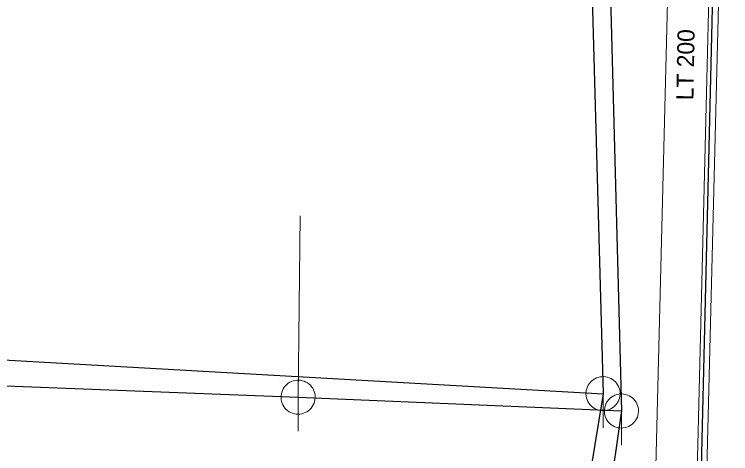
# Model space of a CAD drawing. Extents: x -725153 to -724843, y -978146 to -977794.
# Drawn here: x -724972.4 to -724930.43, y -977958.59 to -977932.83 of the extents above; entities that cross this region are included whole.
import ezdxf

# ---------------------------------------------------------------- set-up
doc = ezdxf.new("R2010")
doc.units = 0
doc.header["$LTSCALE"] = 0.32
doc.layers.add('1', color=7, linetype='Continuous')
for name, color, linetype, lineweight in [('11', 7, 'Continuous', 13), ('13', 7, 'Continuous', 13), ('14', 7, 'Continuous', 25), ('17', 7, 'Continuous', 25), ('2', 7, 'Continuous', 13), ('22', 7, 'Continuous', 13)]:
    doc.layers.add(name, color=color, linetype=linetype, lineweight=lineweight)

msp = doc.modelspace()

# ---------------------------------------------------------------- linework, layer by layer
at = {"layer": '11'}
msp.add_line((-724955.647, -977944.651), (-724955.774, -977955.278), dxfattribs=at)
at = {"layer": '13'}
msp.add_lwpolyline([(-724940.017, -977883.887), (-724940.44, -977904), (-724931.032, -977904.072), (-724932.482, -977963.618)], dxfattribs=at)
at = {"layer": '14'}
for p, q in [((-724938.885, -977919.216), (-724937.906, -977955.074)), ((-724937.758, -977920.649), (-724936.828, -977956.089)), ((-724985.605, -977952.39), (-724937.906, -977955.074)), ((-724987.208, -977954.063), (-724955.774, -977955.278)), ((-724937.906, -977955.074), (-724939.603, -977965.365)), ((-724955.774, -977955.278), (-724936.828, -977956.089)), ((-724936.828, -977956.089), (-724938.046, -977964.432))]:
    msp.add_line(p, q, dxfattribs=at)
at = {"layer": '17'}
msp.add_lwpolyline([(-724932.296, -977965.921), (-724930.809, -977903.881), (-724940.261, -977903.85), (-724939.557, -977875.228), (-724938.671, -977835.46), (-724938.11, -977835.486)], dxfattribs=at)
at = {"layer": '2'}
msp.add_lwpolyline([(-724949.699, -977813.541), (-724947.256, -977811.8), (-724938.004, -977826.019), (-724939.917, -977903.34), (-724930.427, -977903.434), (-724931.995, -977966.488), (-724934.98, -977966.357), (-724933.489, -977906.375), (-724942.987, -977906.14), (-724941.021, -977827.164)], close=True, dxfattribs=at)
at = {"layer": '22'}
for p, q in [((-724955.774, -977957.278), (-724955.773, -977954.278)), ((-724937.906, -977957.074), (-724937.905, -977954.074)), ((-724936.828, -977958.089), (-724936.827, -977955.089))]:
    msp.add_line(p, q, dxfattribs=at)
for points in [[(-724954.774, -977955.278), (-724954.779, -977955.169), (-724954.797, -977955.061), (-724954.827, -977954.955), (-724954.867, -977954.854), (-724954.919, -977954.757), (-724954.981, -977954.667), (-724955.053, -977954.584), (-724955.133, -977954.51), (-724955.221, -977954.444), (-724955.315, -977954.389), (-724955.415, -977954.344), (-724955.52, -977954.311), (-724955.627, -977954.289), (-724955.736, -977954.279), (-724955.846, -977954.281), (-724955.954, -977954.295), (-724956.061, -977954.32), (-724956.164, -977954.357), (-724956.262, -977954.406), (-724956.354, -977954.464), (-724956.44, -977954.533), (-724956.517, -977954.61), (-724956.586, -977954.696), (-724956.645, -977954.788), (-724956.693, -977954.886), (-724956.73, -977954.989), (-724956.756, -977955.096), (-724956.77, -977955.204), (-724956.773, -977955.314), (-724956.763, -977955.423), (-724956.742, -977955.53), (-724956.708, -977955.634), (-724956.664, -977955.734), (-724956.609, -977955.829), (-724956.543, -977955.917), (-724956.469, -977955.997), (-724956.386, -977956.069), (-724956.296, -977956.131), (-724956.2, -977956.183), (-724956.098, -977956.224), (-724955.993, -977956.254), (-724955.885, -977956.272), (-724955.775, -977956.278), (-724955.666, -977956.272), (-724955.558, -977956.254), (-724955.453, -977956.225), (-724955.351, -977956.184), (-724955.254, -977956.132), (-724955.164, -977956.07), (-724955.081, -977955.999), (-724955.006, -977955.919), (-724954.941, -977955.831), (-724954.885, -977955.737), (-724954.841, -977955.637), (-724954.807, -977955.533), (-724954.785, -977955.425), (-724954.775, -977955.316)], [(-724936.906, -977955.074), (-724936.911, -977954.965), (-724936.929, -977954.857), (-724936.959, -977954.751), (-724936.999, -977954.65), (-724937.051, -977954.553), (-724937.113, -977954.463), (-724937.185, -977954.38), (-724937.265, -977954.306), (-724937.353, -977954.24), (-724937.447, -977954.185), (-724937.547, -977954.14), (-724937.652, -977954.107), (-724937.759, -977954.085), (-724937.868, -977954.075), (-724937.978, -977954.077), (-724938.086, -977954.091), (-724938.193, -977954.116), (-724938.296, -977954.153), (-724938.394, -977954.202), (-724938.486, -977954.26), (-724938.572, -977954.329), (-724938.649, -977954.406), (-724938.718, -977954.492), (-724938.777, -977954.584), (-724938.825, -977954.682), (-724938.862, -977954.785), (-724938.888, -977954.892), (-724938.902, -977955), (-724938.905, -977955.11), (-724938.895, -977955.219), (-724938.874, -977955.326), (-724938.84, -977955.43), (-724938.796, -977955.53), (-724938.741, -977955.625), (-724938.675, -977955.713), (-724938.601, -977955.793), (-724938.518, -977955.865), (-724938.428, -977955.927), (-724938.332, -977955.979), (-724938.23, -977956.02), (-724938.125, -977956.05), (-724938.017, -977956.068), (-724937.907, -977956.074), (-724937.798, -977956.068), (-724937.69, -977956.05), (-724937.585, -977956.021), (-724937.483, -977955.98), (-724937.386, -977955.928), (-724937.296, -977955.866), (-724937.213, -977955.795), (-724937.138, -977955.715), (-724937.073, -977955.627), (-724937.017, -977955.533), (-724936.973, -977955.433), (-724936.939, -977955.329), (-724936.917, -977955.221), (-724936.907, -977955.112)], [(-724935.828, -977956.089), (-724935.833, -977955.98), (-724935.851, -977955.872), (-724935.881, -977955.766), (-724935.921, -977955.665), (-724935.973, -977955.568), (-724936.035, -977955.478), (-724936.107, -977955.395), (-724936.187, -977955.321), (-724936.275, -977955.255), (-724936.369, -977955.2), (-724936.469, -977955.155), (-724936.574, -977955.122), (-724936.681, -977955.1), (-724936.79, -977955.09), (-724936.9, -977955.092), (-724937.008, -977955.106), (-724937.115, -977955.131), (-724937.218, -977955.168), (-724937.316, -977955.217), (-724937.408, -977955.275), (-724937.494, -977955.344), (-724937.571, -977955.421), (-724937.64, -977955.507), (-724937.699, -977955.599), (-724937.747, -977955.697), (-724937.784, -977955.8), (-724937.81, -977955.907), (-724937.824, -977956.015), (-724937.827, -977956.125), (-724937.817, -977956.234), (-724937.796, -977956.341), (-724937.762, -977956.445), (-724937.718, -977956.545), (-724937.663, -977956.64), (-724937.597, -977956.728), (-724937.523, -977956.808), (-724937.44, -977956.88), (-724937.35, -977956.942), (-724937.254, -977956.994), (-724937.152, -977957.035), (-724937.047, -977957.065), (-724936.939, -977957.083), (-724936.829, -977957.089), (-724936.72, -977957.083), (-724936.612, -977957.065), (-724936.507, -977957.036), (-724936.405, -977956.995), (-724936.308, -977956.943), (-724936.218, -977956.881), (-724936.135, -977956.81), (-724936.06, -977956.73), (-724935.995, -977956.642), (-724935.939, -977956.548), (-724935.895, -977956.448), (-724935.861, -977956.344), (-724935.839, -977956.236), (-724935.829, -977956.127)]]:
    msp.add_lwpolyline(points, close=True, dxfattribs=at)

# ---------------------------------------------------------------- texts
at = {"layer": '1'}
msp.add_text('LT 200', height=1, rotation=89, dxfattribs=at).set_placement((-724932.61, -977937.876))

doc.saveas('drawing.dxf')
